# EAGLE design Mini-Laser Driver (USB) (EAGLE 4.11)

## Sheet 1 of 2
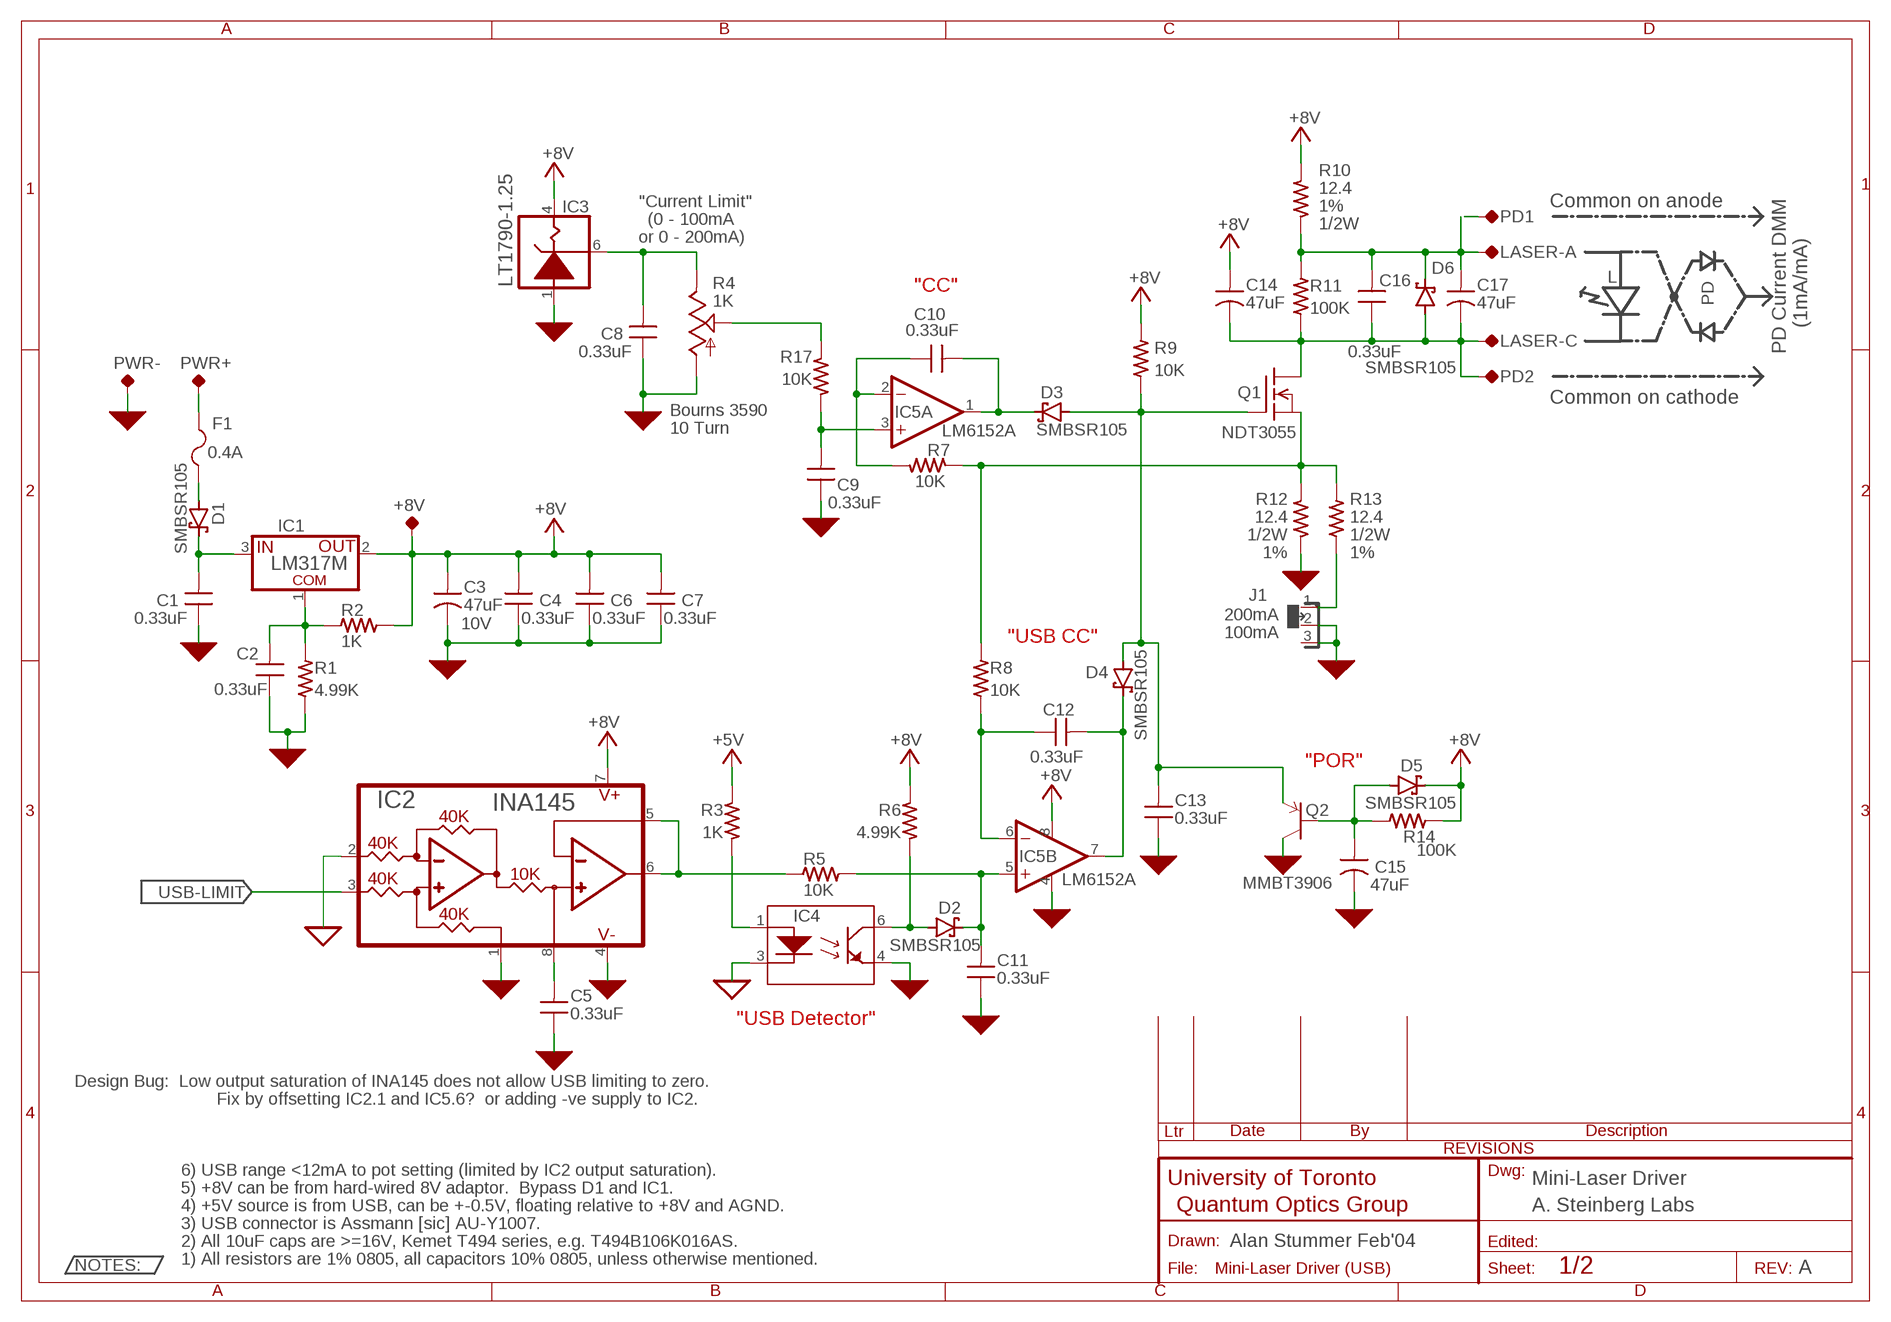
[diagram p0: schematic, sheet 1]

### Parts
+8V  TP-HOLE-0.042  [TP-HOLE]
C1  0.33uF  CAP-V-SMT0805  [0805@1]
C2  0.33uF  CAP-V-SMT0805  [0805@1]
C3  47uF  CAP-POL-EIA-B  [EIA-B]
C4  0.33uF  CAP-V-SMT0805  [0805@1]
C5  0.33uF  CAP-V-0805  [0805]
C6  0.33uF  CAP-V-SMT0805  [0805@1]
C7  0.33uF  CAP-V-SMT0805  [0805@1]
C8  0.33uF  CAP-V-SMT0805  [0805@1]
C9  0.33uF  CAP-V-0805  [0805]
C10  0.33uF  CAP-H-SMT0805  [0805@1]
C11  0.33uF  CAP-V-0805  [0805]
C12  0.33uF  CAP-H-SMT0805  [0805@1]
C13  0.33uF  CAP-V-0805  [0805]
C14  47uF  CAP-POL-EIA-B  [EIA-B]
C15  47uF  CAP-POL-EIA-B  [EIA-B]
C16  0.33uF  CAP-V-0805  [0805]
C17  47uF  CAP-POL-EIA-B  [EIA-B]
D1  SMBSR105  SMBSR105-MSCT  [DO-214AA]
D2  SMBSR105  SMBSR105-MSCT  [DO-214AA]
D3  SMBSR105  SMBSR105-MSCT  [DO-214AA]
D4  SMBSR105  SMBSR105-MSCT  [DO-214AA]
D5  SMBSR105  SMBSR105-MSCT  [DO-214AA]
D6  SMBSR105  SMBSR105-MSCT  [DO-214AA]
F1  0.4A  FUSE5X20-2  [FUSE5X20-2]
IC1  LM317M  LM317D2  [D2PAK]
IC2  INA145UA  [SOIC-8]
IC3  LT1790-1.25  LT1790BCS6-1.25  [SOT23-6]
IC4  TLP181  [SOIC-6]
IC5  LM6152A  LT1807CS8  [SOIC-8]
J1  JUMPER-1X3-3  [JUMPER-3]
LASER-A  TP-HOLE-0.042  [TP-HOLE]
LASER-C  TP-HOLE-0.042  [TP-HOLE]
PD1  TP-HOLE-0.042  [TP-HOLE]
PD2  TP-HOLE-0.042  [TP-HOLE]
PWR+  TP-HOLE-0.042  [TP-HOLE]
PWR-  TP-HOLE-0.042  [TP-HOLE]
Q1  NDT3055  [SOT223]
Q2  MMBT3906  BJT-PNP-SOT23  [SOT23]
R1  4.99K  R-V-0805  [0805]
R2  1K  R-H-0805  [0805]
R3  1K  R-V-0805  [0805]
R4  1K  POT-3590  [3590_BOURNS]
R5  10K  R-H-0805  [0805]
R6  4.99K  R-V-0805  [0805]
R7  10K  R-H-0805  [0805]
R8  10K  R-V-0805  [0805]
R9  10K  R-V-0805  [0805]
R10  12.4  R-V-THRU  [PASSIVE_0.4"]
R11  100K  R-V-0805  [0805]
R12  12.4  R-V-THRU  [PASSIVE_0.4"]
R13  12.4  R-V-THRU  [PASSIVE_0.4"]
R14  100K  R-H-0805  [0805]
R17  10K  R-V-0805  [0805]

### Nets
+1.23V: C8.2 IC3.6(OUT) R4.CW
+5V [Fat Track 0.025"]: R3.2 ; also sheet 2
+8V [Fat Track 0.025"]: +8V.P$1(TP) C3.2(POS) C4.2 C6.2 C7.2 C14.2(POS) D5.K(C) IC1.2(VO) IC2.7(V+) IC3.4(IN) IC5.8(V+) R2.2 R6.2 R9.2 R10.2 R14.2
AGND [Fat Track 0.025"]: C1.1 C2.1 C3.1(NEG) C4.1 C5.1 C6.1 C7.1 C8.1 C9.1 C11.1 C13.1 C15.1(NEG) IC2.1(IN-REF) IC2.4(V-) IC3.1(COM) IC4.4(E) IC5.4(V-) J1.2 J1.3 PWR-.P$1(TP) Q2.3(C) R1.1 R4.CCW R12.1
CC-LEVEL: C9.2 IC5.3(A:+IN) R17.1
GND2 [Fat Track 0.025"]: IC2.2(IN-) IC4.3(K) ; also sheet 2
I-LASER [Fat Track 0.025"]: Q1.3(S) R7.1 R8.2 R12.2 R13.2
LASER-A [Fat Track 0.025"]: C16.2 C17.2(POS) D6.K(C) LASER-A.P$1(TP) PD1.P$1(TP) R10.1 R11.2
LASER-C [Fat Track 0.025"]: C14.1(NEG) C16.1 C17.1(NEG) D6.A LASER-C.P$1(TP) PD2.P$1(TP) Q1.2(D) R11.1
LIMIT: C13.2 D3.A D4.A Q1.1(G) Q2.2(E) R9.1
N$1: C10.1 D3.K(C) IC5.1(A:OUT)
N$2 [Fat Track 0.025"]: D2.A IC4.6(C) R6.1
N$3: IC2.5(RG) IC2.6(OUT) R5.1
N$4 [Fat Track 0.025"]: J1.1 R13.1
N$5: C10.2 IC5.2(A:-IN) R7.2
N$7 [Fat Track 0.025"]: C5.2 IC2.8(VOI)
N$8 [Fat Track 0.025"]: IC4.1(A) R3.1
N$11 [Fat Track 0.025"]: D1.A F1.1(1A)
N$15: C2.2 IC1.1(COM) R1.2 R2.1
N$16: C12.1 D4.K(C) IC5.7(B:OUT)
N$17: C12.2 IC5.6(B:-IN) R8.1
N$20 [Fat Track 0.025"]: C1.2 D1.K(C) IC1.3(VI)
N$24 [Fat Track 0.025"]: F1.2(2A) PWR+.P$1(TP)
N$25 [Fat Track 0.025"]: R4.W R17.2
POR: C15.2(POS) D5.A Q2.1(B) R14.1
USB-CC-LIMIT: C11.2 D2.K(C) IC5.5(B:+IN) R5.2
Unconnected: IC2.3(IN+)

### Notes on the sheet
- PD Current DMM
- "Current Limit" | 1% | Common on anode
- (0 - 100mA | 1/2W
- or 0 - 200mA)
- L
- "CC"
- PD
- (1mA/mA)
- Common on cathode
- Bourns 3590
- 10 Turn
- 1/2W | 1/2W
- 1% | 1%
- 200mA
- 10V
- "USB CC" | 100mA
- "POR"
- "USB Detector"
- Design Bug:  Low output saturation of INA145 does not allow USB limiting to zero.
- Fix by offsetting IC2.1 and IC5.6?  or adding -ve supply to IC2.
- 6) USB range <12mA to pot setting (limited by IC2 output saturation).
- Mini-Laser Driver
- 5) +8V can be from hard-wired 8V adaptor.  Bypass D1 and IC1.
- 4) +5V source is from USB, can be +-0.5V, floating relative to +8V and AGND. | A. Steinberg Labs
- 3) USB connector is Assmann [sic] AU-Y1007.
- 2) All 10uF caps are >=16V, Kemet T494 series, e.g. T494B106K016AS. | Alan Stummer Feb'04
- 1) All resistors are 1% 0805, all capacitors 10% 0805, unless otherwise mentioned.
- A

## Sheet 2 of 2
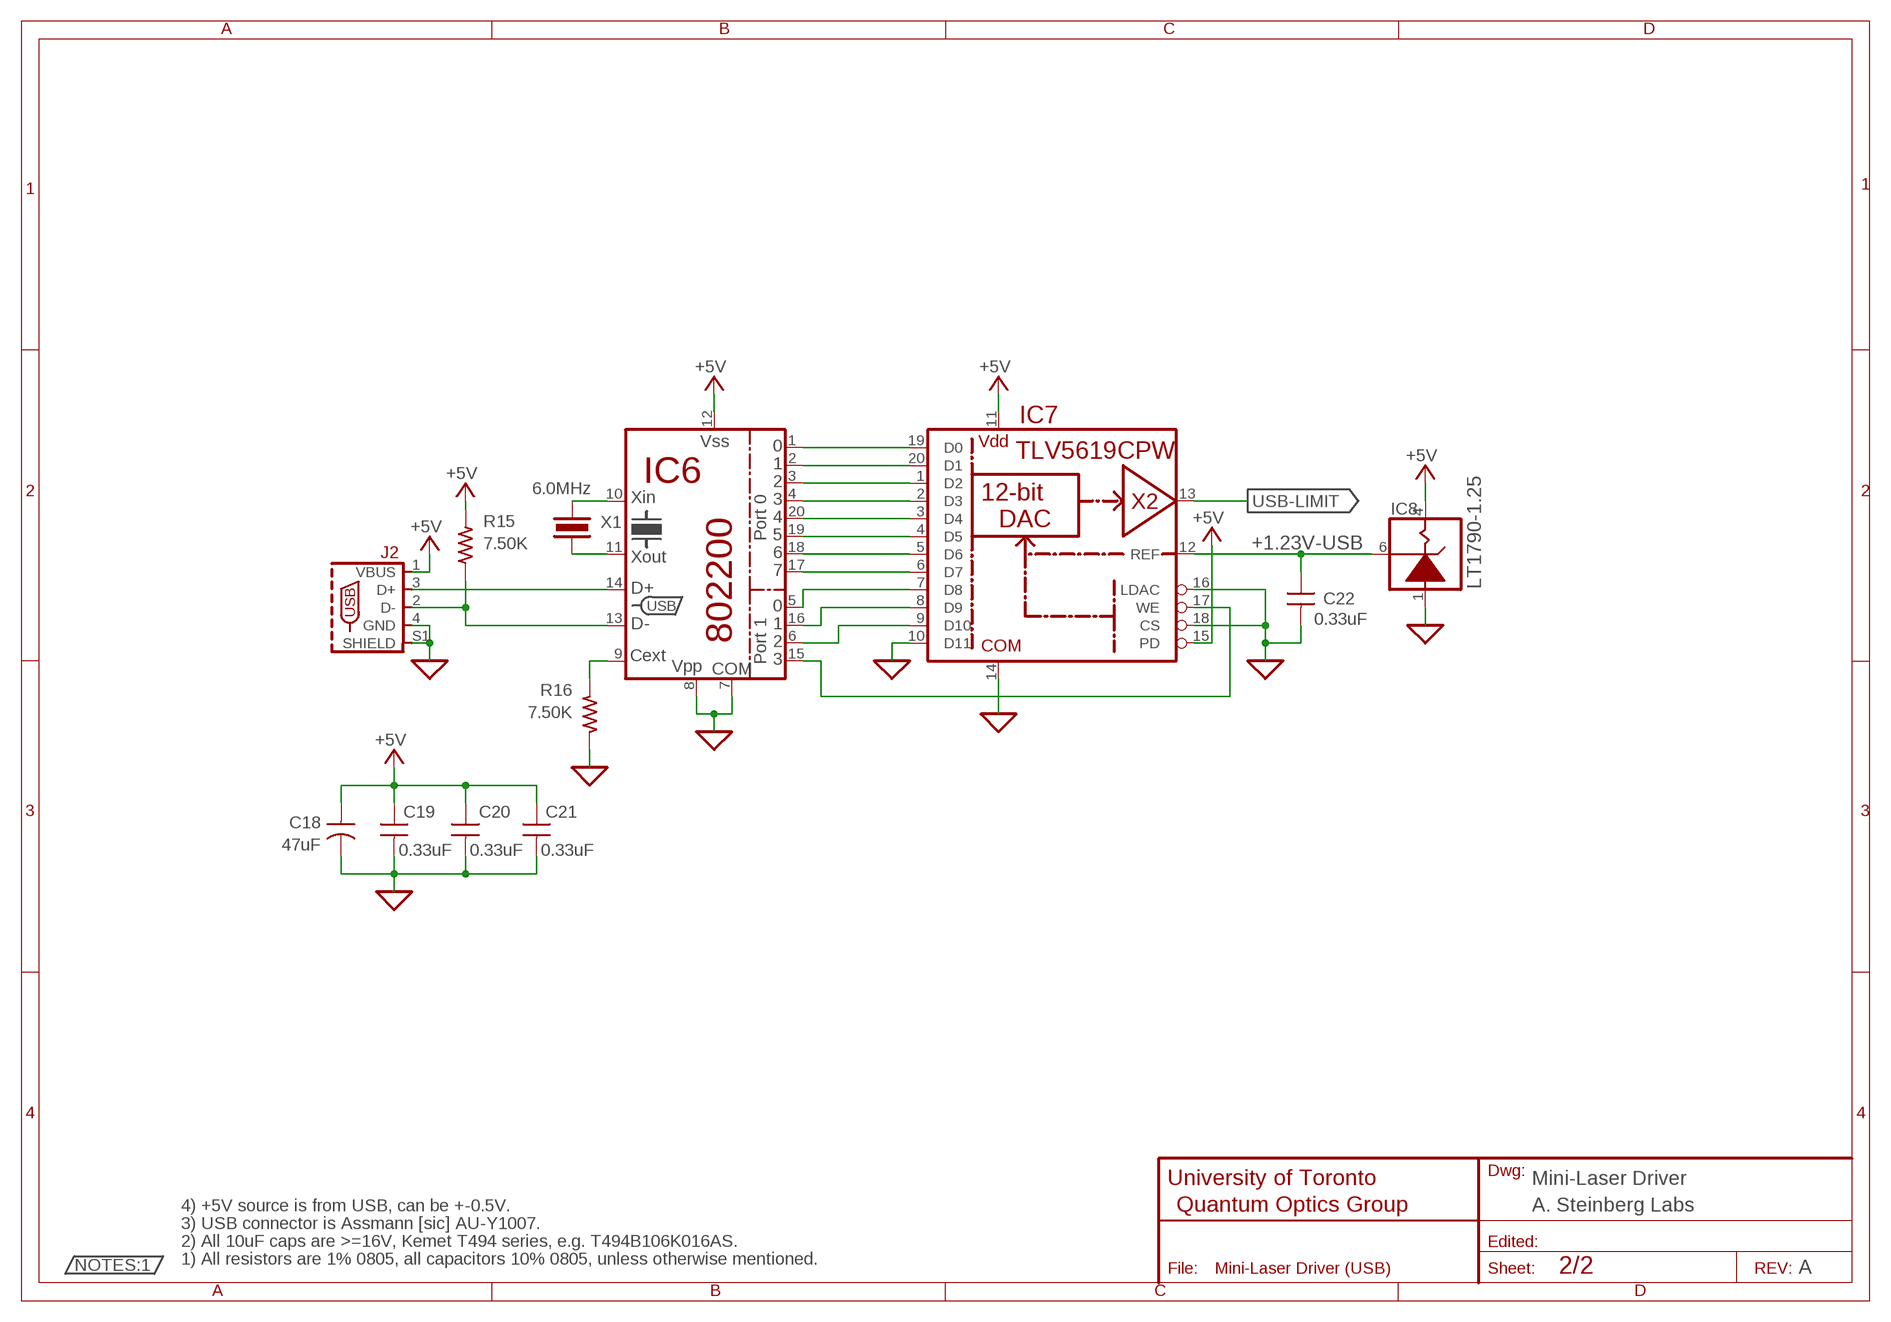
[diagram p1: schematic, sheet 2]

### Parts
C18  47uF  CAP-POL-EIA-B  [EIA-B]
C19  0.33uF  CAP-H-0805  [0805]
C20  0.33uF  CAP-H-0805  [0805]
C21  0.33uF  CAP-H-0805  [0805]
C22  0.33uF  CAP-H-0805  [0805]
IC6  802200  802200(DELCOMUSB)-SO20  [SOIC-20W]
IC7  TLV5619CPW  [TSSOP-20]
IC8  LT1790-1.25  LT1790BCS6-1.25  [SOT23-6]
J2  AU-Y1007-USB-B  [CONN-USB_AU-Y1007]
R15  7.50K  R-V-0805  [0805]
R16  7.50K  R-V-0805  [0805]
X1  6.0MHz  XTAL/RESONATOR-P  [RESONATOR-P]

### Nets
+1.23V-USB: C22.2 IC7.12(REF) IC8.6(OUT)
+5V [Fat Track 0.025"]: C18.2(POS) C19.2 C20.2 C21.2 IC6.12(VCC) IC7.11(VDD) IC7.15(PD) IC8.4(IN) J2.1(VBUS) R15.2 ; also sheet 1
GND2 [Fat Track 0.025"]: C18.1(NEG) C19.1 C20.1 C21.1 C22.1 IC6.7(COM) IC6.8(VPP) IC7.10(D11) IC7.14(COM) IC7.16(LDAC) IC7.18(CS) IC8.1(COM) J2.4(GND) J2.S1(SHIELD) R16.1 ; also sheet 1
N$6: IC6.9(CEXT) R16.2
N$46: IC6.10(XTL1) X1.2(X2)
N$47: IC6.11(XTL2) X1.1(X1)
N$49: IC6.1(P0.0) IC7.19(D0)
N$50: IC6.2(P0.1) IC7.20(D1)
N$51: IC6.3(P0.2) IC7.1(D2)
N$52: IC6.4(P0.3) IC7.2(D3)
N$53: IC6.20(P0.4) IC7.3(D4)
N$54: IC6.19(P0.5) IC7.4(D5)
N$55: IC6.18(P0.6) IC7.5(D6)
N$56: IC6.17(P0.7) IC7.6(D7)
N$57: IC6.5(P1.0) IC7.7(D8)
N$58: IC6.16(P1.1) IC7.8(D9)
N$59: IC6.6(P1.2) IC7.9(D10)
USB-D+1: IC6.14(D+) J2.3(D+)
USB-D-1: IC6.13(D-) J2.2(D-) R15.1
USB-LIMIT: IC7.13(OUT) ; also sheet 1
~WE1: IC6.15(P1.3) IC7.17(WE)

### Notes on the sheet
- Mini-Laser Driver
- 4) +5V source is from USB, can be +-0.5V. | A. Steinberg Labs
- 3) USB connector is Assmann [sic] AU-Y1007.
- 2) All 10uF caps are >=16V, Kemet T494 series, e.g. T494B106K016AS.
- 1) All resistors are 1% 0805, all capacitors 10% 0805, unless otherwise mentioned.
- A

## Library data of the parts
+8V LASER-A LASER-C PD1 PD2 PWR+ PWR- = 0-UofT-Physics:TP: Testpoint, test point on schematic, small pad on PCB.
C1 C2 C4 C6-C8 = 0-UofT-Physics:CAP-V-SMT*: Cap, SMT 0805
C3 C14 C15 C17 C18 = 0-UofT-Physics:CAP-POL-: Capacitor, Polarized, electrolytic (tantalum)l.
C5 C9 C11 C13 C16 = 0-UofT-Physics:CAP-V-: Cap, SMT, 0402 to 1206
C10 C12 = 0-UofT-Physics:CAP-H-SMT*: Cap, SMT 0805
C19-C22 = 0-UofT-Physics:CAP-H-: Cap, SMT, 0402 to 1206
D1-D6 = 0-UofT-Physics:SMBSR105: SMBSR105, MCC, Schottky 50V 1A SMT, general purpose, Vf=0.4V@1A, Ir=3uA@5V@25°(poor).
F1 = 0-UofT-Physics:FUSE: Fuse
IC1 = 0-UofT-Physics:LM317: LM317, bandgap based adjustable regulator.
IC2 = 0-UofT-Physics:INA145: INA145, Burr-Brown/T.I., instrumentation amp, CMR >85dB, 2(V-) < Vcm < 2(V+)-2.
IC3 IC8 = 0-UofT-Physics:LT1790: LT1790, series reference in SOT-23-6. From 1.25V to 5.0V with common binary voltages. Likes 1uF or more load, 0.1uF or more source.
IC4 = 0-UofT-Physics:TLP181: Opto-coupler, Toshiba, general purpose, 3.75KV, Vce 50%, If < 50mA, 150mW.
IC5 = 0-UofT-Physics:LT1807*: Op Amp, dual, single supply, RRIO, fast (GBW 350MHz, 100V/uS). Great part, but Ib = 4uA max.
IC6 = 0-UofT-Physics:802200(DELCOMUSB): 802200 USB Peripheral, Delcom, quick and dirty USB 1.0 peripheral solution.
IC7 = 0-UofT-Physics:TLV5619
J1 = 0-UofT-Physics:JUMPER-1X3: Jumper, header, SIP on 0.1" grid, for option selection.
J2 = 0-UofT-Physics:AU-Y1007
Q1 = 0-UofT-Physics:NDT3055: NDT3055, Fairchild, N-channel MOSFET. SOT-223, 4A, 60V, 3Wmax, 0.1 Ohm at Vgs=10V.
Q2 = 0-UofT-Physics:BJT-PNP: PNP BJT, generic, p/n defined by VALUE field. E.g. Fairchild MMBT3906 (abs max 40V, 200mA. hFE>80@10mA.
R1 R3 R6 R8-R13 R15-R17 = 0-UofT-Physics:R-V-*: Resistor, SMT, vertical symbol
R2 R5 R7 R14 = 0-UofT-Physics:R-H-*: Resistor, SMT, horizontal symbol
R4 = 0-UofT-Physics:POT: Pot, regular or trimpot
X1 = 0-UofT-Physics:XTAL/RESONATOR: Crystal or Reonator. Besure to verify package, especially SMT pads sizes and locations.

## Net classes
1 Fat Track 0.025": width 0.635 mm, drill 0.254 mm

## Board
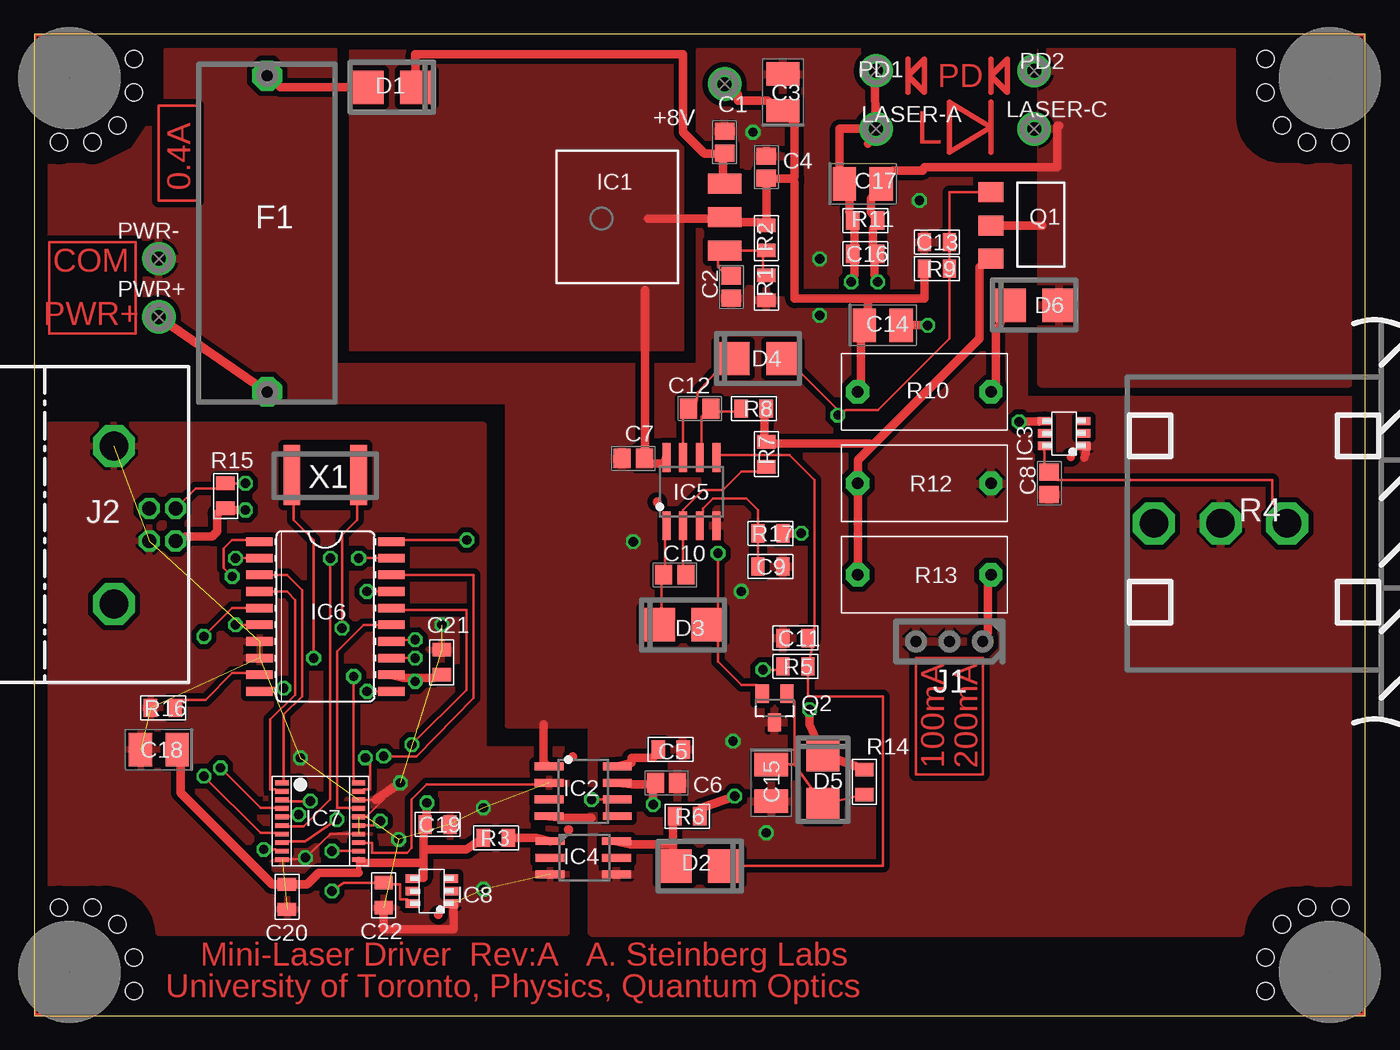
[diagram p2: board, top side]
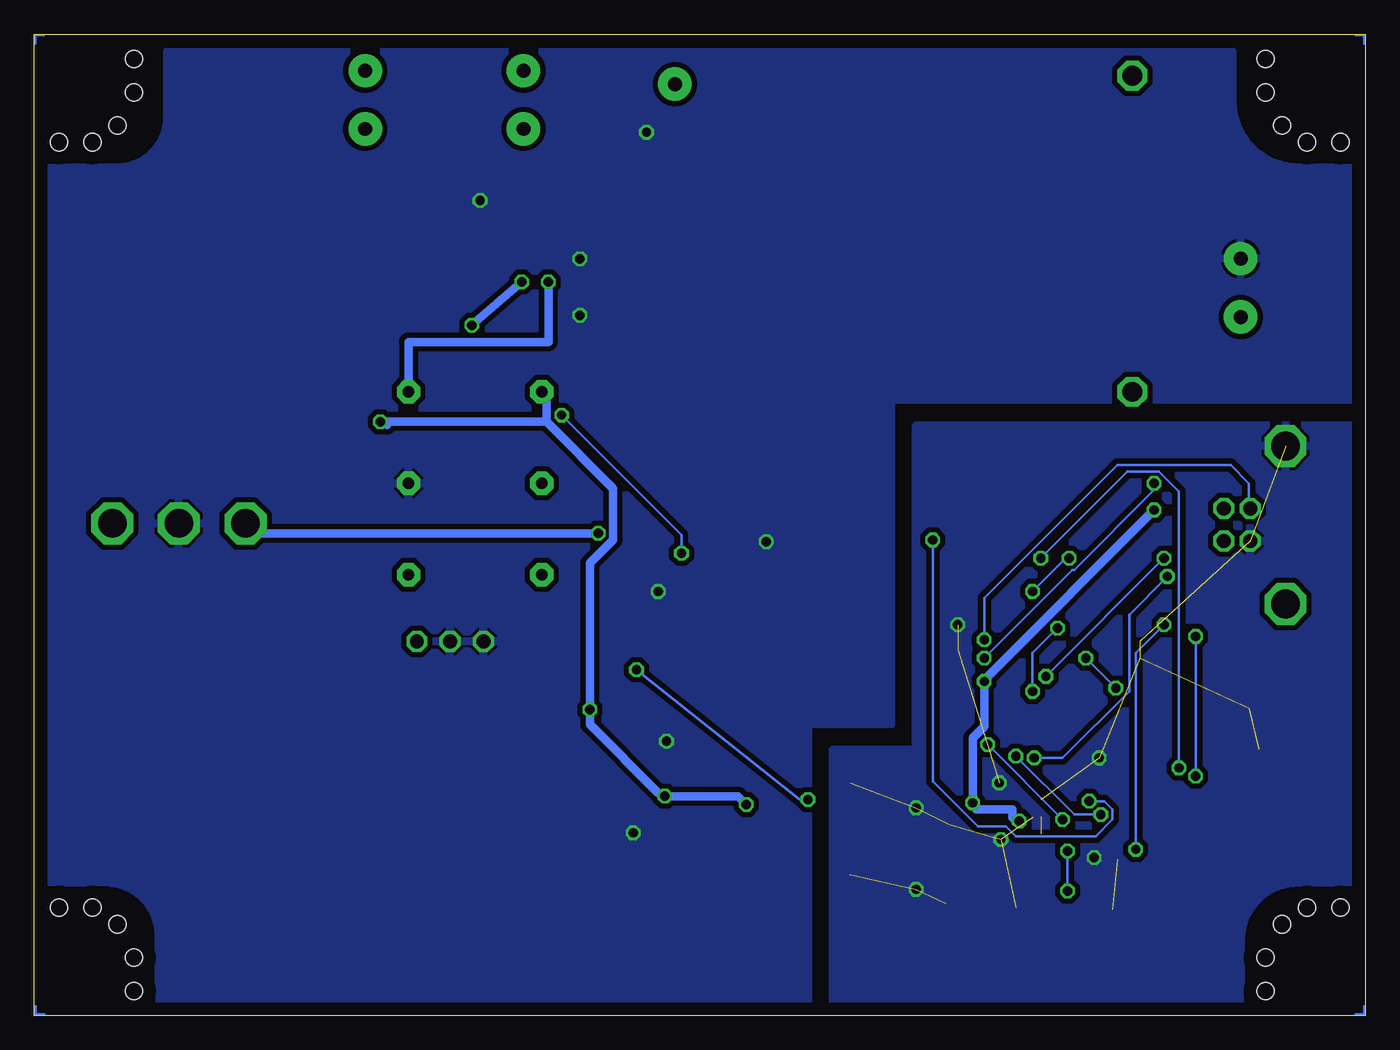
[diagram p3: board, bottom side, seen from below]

Size 101.6 x 74.93 mm. Coordinates in mm from the lower left corner, seen from the top.
Outline: 0,0 101.6,0 101.6,74.93 0,74.93 0,0
Copper layers (1*16): Top 0.035mm / dielectric 1.5mm / Bottom 0.035mm
Design rules "default": minimum track width 8mil, minimum drill 28mil, track to track 8mil, track to pad 8mil, pad to pad 8mil, via to via 8mil, smd to smd 8mil, copper to edge 40mil, drill to drill 8mil, minimum pad ring 10mil, minimum via ring 8mil, stop-mask expansion 4mil, vias tented up to drill 0mil, thermal gap 10mil
Holes 1.32 mm at 99.69,8.26 93.98,1.91 95.25,6.99 97.16,8.26 93.98,4.45 1.91,8.26 7.62,1.91 6.35,6.99 4.45,8.26 7.62,4.45 1.91,66.67 7.62,73.03 6.35,67.94 4.45,66.67 7.62,70.48 99.69,66.67 93.98,73.03 95.25,67.94 97.16,66.67 93.98,70.48

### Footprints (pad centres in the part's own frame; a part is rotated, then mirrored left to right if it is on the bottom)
TP-HOLE = drill 1.067 pad 2.54 round: P$1 0,0
0805@1 = smd 1.3 x 1.5: 1 -0.85,0; 2 0.85,0
EIA-B = smd 1.778 x 2.54: 1 -1.4,0; 2 1.4,0
0805 = smd 1.016 x 1.397: 1 -1.905,0; 2 0,0
DO-214AA = smd 2.54 x 2.54: A -1.905,0; K 1.905,0
FUSE5X20-2 = drill 1.511 octagon: 1 -12.065,0; 2 12.065,0
D2PAK = smd 1.524 x 2.54: 1 -2.54,-2.54; 2 0,-2.54; 3 2.54,-2.54
SOIC-8 = smd 0.6 x 2.2: 1 -1.27,-2.6; 2 0,-2.6; 3 1.27,-2.6; 4 2.54,-2.6; 5 2.54,2.6; 6 1.27,2.6; 7 0,2.6; 8 -1.27,2.6
SOT23-6 = smd 0.635 x 0.991: 1 -0.95,-0.099; 2 0,-0.099; 3 0.95,-0.099; 4 0.95,2.901; 5 0,2.901; 6 -0.95,2.901
SOIC-6 = smd 0.6 x 2.2: 1 -1.27,-2.54; 2 0,-2.54; 3 1.27,-2.54; 4 1.27,2.54; 5 0,2.54; 6 -1.27,2.54
SOIC-20W = smd 0.66 x 2.032: 1 -5.715,-5.029; 2 -4.445,-5.029; 3 -3.175,-5.029; 4 -1.905,-5.029; 5 -0.635,-5.029; 6 0.635,-5.029; 7 1.905,-5.029; 8 3.175,-5.029; 9 4.445,-5.029; 10 5.715,-5.029; 11 5.715,5.029; 12 4.445,5.029; 13 3.175,5.029; 14 1.905,5.029; 15 0.635,5.029; 16 -0.635,5.029; 17 -1.905,5.029; 18 -3.175,5.029; 19 -4.445,5.029; 20 -5.715,5.029
TSSOP-20 = smd 0.356 x 1.016: 1 0,-5.85; 2 0.65,-5.85; 3 1.3,-5.85; 4 1.95,-5.85; 5 2.6,-5.85; 6 3.25,-5.85; 7 3.9,-5.85; 8 4.55,-5.85; 9 5.2,-5.85; 10 5.85,-5.85; 11 5.85,0; 12 5.2,0; 13 4.55,0; 14 3.9,0; 15 3.25,0; 16 2.6,0; 17 1.95,0; 18 1.3,0; 19 0.65,0; 20 0,0
JUMPER-3 = drill 1.067 octagon: 1 0,2.54; 2 0,0; 3 0,-2.54
CONN-USB_AU-Y1007 = drill 1.067 octagon: 1 2.5,0; 2 0,0; 3 0,-2; 4 2.5,-2 | drill 2.184 octagon: S1 -4.75,-4.7; S2 7.3,-4.7
SOT223 = smd 1.524 x 1.905: 1 -2.54,-2.54; 2 0,-2.54; 3 2.54,-2.54
SOT23 = smd 1 x 1.4: 1 -0.95,-1.1; 2 0.95,-1.1; 3 0,1.1
3590_BOURNS = drill 2.184 octagon: CCW -12.065,0; CW -6.985,0; W -17.145,0
PASSIVE_0.4" = drill 0.889 pad 1.778 octagon: 1 -5.08,0; 2 5.08,0
RESONATOR-P = smd 1.27 x 4.572: 1 -2.54,0; 2 2.54,0

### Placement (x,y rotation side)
+8V  52.7,71.12 90 top
C1  52.7,66.67 270 top
C2  53.21,55.63 90 top
C3  57.15,70.48 270 top
C4  55.88,64.77 270 top
C5  47.62,20.32 180 top
C6  48.26,17.78 180 top
C7  45.72,42.55 0 top
C8  77.47,40.64 90 top
C9  55.24,34.29 180 top
C10  48.9,33.66 0 top
C11  59.05,28.83 0 top
C12  50.8,46.35 0 top
C13  69.85,59.05 0 top
C14  64.77,52.7 180 top
C15  56.26,17.78 90 top
C16  62.48,58.17 180 top
C17  63.25,63.5 180 top
C18  9.53,20.32 0 top
C19  29.84,14.61 180 top
C20  19.3,10.03 90 top
C21  31.11,26.04 270 top
C22  26.67,10.16 90 top
D1  27.3,70.87 0 top
D2  50.8,11.43 0 top
D3  49.53,29.84 180 top
D4  55.24,50.16 180 top
D5  60.2,18.03 90 top
D6  76.33,54.23 180 top
F1  17.78,59.69 270 top
IC1  50.16,60.96 90 top
IC2  41.91,17.78 270 top
IC3  80.01,44.45 90 top
IC4  41.91,12.06 270 top
IC5  49.53,40.01 0 top
IC6  22.23,30.48 270 top
IC7  24.77,17.78 270 top
IC8  31.75,9.53 90 top
J1  69.85,28.57 270 top
J2  10.79,38.73 270 top
LASER-A  64.26,67.69 90 top
LASER-C  76.33,67.69 0 top
PD1  64.26,72.14 90 top
PD2  76.33,72.14 90 top
PWR+  9.53,53.34 0 top
PWR-  9.53,57.78 0 top
Q1  75.56,60.33 270 top
Q2  56.52,23.5 180 top
R1  55.88,56.52 90 top
R2  55.88,60.33 90 top
R3  34.29,13.59 180 top
R4  102.62,37.59 0 top
R5  59.05,26.67 0 top
R6  50.8,15.24 0 top
R7  55.88,41.91 270 top
R8  55.88,46.35 0 top
R9  67.94,57.02 180 top
R10  67.94,47.62 180 top
R11  62.48,60.71 180 top
R12  67.94,40.64 180 top
R13  67.94,33.66 180 top
R14  63.37,18.8 90 top
R15  14.61,38.73 270 top
R16  10.79,23.5 0 top
R17  57.15,36.83 0 top
U$29  [TARGET]  not placed on the board
U$30  [TARGET]  not placed on the board
U$31  [TARGET]  not placed on the board
U$32  [TITLEBLOCK_PCB]  not placed on the board
X1  22.23,41.27 180 top

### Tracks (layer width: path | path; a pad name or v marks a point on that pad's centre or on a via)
+1.23V
  Top 0.203: IC3.6 77.09,43.31 77.09,42.04 C8.2 78.11,40.89 94.49,40.89 94.49,39.24 R4.CW
+1.23V-USB  (via drill 0.71)
  Top 0.203: IC8.6 28.45,8.89 27.94,8.89 27.94,10.03 27.3,10.03 C22.2 23.62,10.16 v22.73,9.53 | v22.73,12.57 IC7.12
  Bottom 0.203: v22.73,9.53 v22.73,12.57
+5V  (via drill 0.71)
  Top 0.203: IC7.15 26.09,14.53 v26.42,14.86 | IC7.11 25.15,11.68
  Top 0.406: 24.77,10.92 IC7.11
  Top 0.635: C18.2 11.18,19.18 11.18,17.02 18.16,10.03 C20.2 20.83,10.03 21.72,10.92 24.77,10.92 | J2.1 11.56,36.58 13.59,36.58 13.97,36.96 13.97,38.35 R15.2 15.24,38.61 v16.13,38.61 | 29.08,25.78 28.19,25.78 IC6.12 | 29.08,25.78 30.48,25.78 C21.2 | 29.72,11.68 29.72,10.54 IC8.4 | 29.72,11.68 29.72,12.7 | 29.72,12.7 29.72,13.97 C19.2 29.97,15.24 v29.97,16.26 | 25.15,11.68 29.72,11.68 | R3.2 33.02,12.7 29.72,12.7 | v29.08,25.53 29.08,25.78
  Bottom 0.635: v16.13,38.61 28.83,25.91 v29.08,25.53 29.08,22.1 29.97,21.21 v29.97,16.26 29.72,15.75 26.92,15.75 26.92,15.11 v26.42,14.86
+8V  (via drill 0.71)
  Top 0.635: v53.47,16.76 50.93,15.88 R6.2 | v47.24,16.13 47.24,17.14 C6.2 46.86,17.65 45.59,17.65 IC2.7 | 63.63,54.74 67.94,54.74 R9.2 | 63.63,54.74 63.63,53.85 C14.2 63.12,51.56 63.12,48.39 R10.2 | +8V.P$1 53.72,70.36 53.72,69.85 56.01,69.85 C3.2 58.04,68.2 58.04,64.01 57.91,63.88 | IC5.8 48.01,42.16 47.12,42.16 C7.2 46.61,43.18 46.61,55.37 | 46.86,60.83 51.82,60.83 IC1.2 53.59,60.58 55.24,60.58 R2.2 C4.2 56.52,63.88 57.91,63.88 | 63.63,54.74 58.04,54.74 58.04,63.63 57.91,63.88 | R14.2 D5.K 59.18,22.23 v59.18,23.37 | v75.18,45.34 76.71,45.34 IC3.4
  Bottom 0.635: v47.24,16.13 47.88,16.76 v53.47,16.76 53.98,17.02 59.18,22.23 v59.18,23.37 59.18,34.54 57.4,36.32 57.4,40.26 62.48,45.34 | 62.48,45.34 62.48,46.86 R10.2 | 62.48,45.34 74.68,45.34 | 74.68,45.34 75.06,45.34 | v75.18,45.34 74.68,45.09 74.68,45.34
  pour Top (isolate 0.406): 24.13,73.66 24.13,50.8 49.53,50.8 49.53,73.66
AGND  (via drill 0.71)
  Top 0.635: 38.86,22.23 38.86,19.3 IC2.1 | 42.55,15.11 40.39,15.11 IC2.4 | IC3.1 80.26,43.31 80.26,42.93 80.15,42.62
  other vias: 45.72,36.2 53.98,32.38 59.94,57.78 59.94,53.47 53.34,20.95 55.88,13.97 54.86,67.44 67.56,62.23
  pour Bottom (isolate 0.406): 10.16,73.66 10.16,69.85 arc-90 5.08,64.77 0.64,64.77 0.64,46.99 36.2,46.99 36.2,22.23 42.55,22.23 42.55,0.64 92.08,0.64 92.08,6.35 arc-90 96.52,10.16 100.97,10.16 100.97,64.77 95.25,64.77 arc-90 91.44,68.58 91.44,73.66
  pour Top (isolate 0.406): 50.8,73.66 50.8,49.53 22.86,49.53 22.86,73.66 10.16,73.66 10.16,69.85 7.62,66.04 5.08,64.77 0.64,64.77 0.64,46.99 36.2,46.99 36.2,22.23 42.55,22.23 42.55,6.35 92.08,6.35 arc-90 96.52,10.16 100.97,10.16 100.97,46.99 75.56,46.99 75.56,73.66
CC-LEVEL
  Top 0.203: C9.2 R17.1 55.24,38.61 54.36,39.5 51.82,39.5 51.05,38.73 51.05,38.48 IC5.3
GND2  (via drill 0.71)  (18 unrouted)
  Top 0.203: IC7.14 23.15,13.88 22.61,13.84 v20.7,12.06 19.93,11.94 IC7.10 | 26.07,16.48 IC7.18 | IC7.16 25.34,15.18 v27.94,17.78 | 32,8.57 IC8.1
  Top 0.635: v27.94,17.78 26.07,16.48 | 32,8.57 32,6.6 26.67,6.6 C22.1
  other vias: 34.29,15.88 31.11,29.84 27.81,13.46 20.32,19.68 34.29,9.65
  pour Top (isolate 0.406): 0,45.09 0,10.16 5.08,10.16 arc-90 9.53,6.35 40.64,6.35 40.64,20.32 34.29,20.32 34.29,45.09
  pour Bottom (isolate 0.406): 0,45.09 0,10.16 5.08,10.16 arc-90 9.53,5.71 9.53,0.64 40.64,0.64 40.64,20.32 34.29,20.32 34.29,45.09
I-LASER
  Top 0.635: R8.2 55.75,45.72 55.75,44.2 R7.1 56.52,43.69 63.75,43.69 63.94,43.5 | 63.94,43.5 62.87,42.42 R12.2 R13.2 | 63.94,43.5 72.14,51.69 72.14,57.15 Q1.3
LASER-A  (via drill 0.71)
  Top 0.635: PD1.P$1 64.14,71.75 LASER-A.P$1 | D6.K 73.41,52.2 73.41,48.39 R10.1 | LASER-A.P$1 63.63,66.55 | v62.36,56.01 62.61,56.52 62.61,57.53 C16.2 62.61,58.8 62.61,60.07 R11.2 62.23,61.34 62.23,62.36 C17.2 61.47,64.64 61.47,67.69 LASER-A.P$1
  Bottom 0.635: v62.36,56.01 62.36,51.44 73.03,51.44 R10.1
LASER-C  (via drill 0.71)
  Top 0.635: Q1.2 76.96,60.33 | C14.1 v68.2,52.7 | 78.23,67.94 78.11,67.94 78.11,64.77 67.94,64.77 67.82,64.52 65.53,64.52 C17.1 63.88,62.36 63.88,61.34 R11.1 64.01,60.07 64.01,58.8 C16.1 64.14,57.53 64.14,56.52 v64.39,56.01
  Bottom 0.635: v68.2,52.7 v64.39,56.01
  pour Top (isolate 0.406): 76.83,73.66 76.83,48.26 100.33,48.26 100.33,64.77 95.25,64.77 arc-90 91.44,68.58 91.44,73.66
LIMIT  (via drill 0.71)
  Top 0.203: Q2.2 55.12,25.27 53.98,25.27 52.2,27.05 52.2,28.7 D3.A 52.2,30.99 v52.2,35.31 | 61.53,46.04 61.98,46.23 64.39,46.23 69.85,51.69 R9.1 C13.2 69.85,62.87 Q1.1 | 61.53,46.04 58.55,49.02 57.66,49.02 D4.A | v61.34,45.85 61.53,46.04
  Bottom 0.203: v52.2,35.31 52.2,36.7 v61.34,45.85
N$1
  Top 0.203: D3.K 47.88,30.99 47.88,33.02 C10.1 48.13,34.29 48.13,36.32 IC5.1
N$2
  Top 0.635: 48.77,13.08 48.77,12.57 D2.A | 48.77,13.08 48.77,14.61 R6.1 | IC4.6 45.47,13.08 48.77,13.08
N$3  (via drill 0.71)
  Top 0.203: v55.63,26.42 56.77,26.42 R5.1 | v42.55,16.51 IC2.6 43.69,16.26 43.69,15.49 IC2.5
  Bottom 0.203: v55.63,26.42 43.18,16.51 v42.55,16.51
N$4
  Top 0.635: J1.1 72.77,29.21 72.77,32.89 R13.1
N$5
  Top 0.203: R7.2 55.24,41.53 53.98,41.53 52.58,40.13 51.05,40.13 49.53,38.61 IC5.2 49.53,34.29 C10.2
N$6
  Top 0.203: R16.2 11.18,24.13 13.08,24.13 15.11,26.16 16.26,26.16 IC6.9
N$7
  Top 0.635: C5.2 47.24,19.68 45.59,19.68 45.59,19.3 IC2.8
N$8
  Top 0.635: R3.1 38.35,13.59 IC4.1
N$9
  Bottom 0.203: 0.1,0.74 0.1,0.1 0.74,0.1
N$10
  Top 0.203: 0.1,0.74 0.1,0.1 0.74,0.1
N$11
  Top 0.635: D1.A 18.8,70.87 F1.1
N$12
  Bottom 0.203: 0.74,74.83 0.1,74.83 0.1,74.19
N$13
  Top 0.203: 0.74,74.83 0.1,74.83 0.1,74.19
N$14
  Bottom 0.203: 101.5,74.19 101.5,74.83 100.86,74.83
N$15
  Top 0.203: R1.2 55.63,56.9 55.63,58.04 R2.1 IC1.1 52.2,57.78 52.2,57.15 52.83,56.52 52.83,56.48 C2.2
N$16
  Top 0.203: IC5.7 49.53,45.72 C12.1 50.55,46.86 50.67,47.62 51.94,49.02 D4.K
N$17
  Top 0.203: R8.1 53.59,46.1 52.2,46.1 C12.2 51.05,45.85 50.93,45.72 50.93,43.69 IC5.6
N$20
  Top 0.635: IC1.3 52.58,64.14 52.58,65.28 C1.2 52.7,65.79 51.18,65.79 49.53,67.44 49.53,73.41 29.08,73.41 D1.K
N$21
  Top 0.203: 101.5,74.19 101.5,74.83 100.86,74.83
N$22
  Bottom 0.203: 100.84,0.1 101.47,0.1 101.47,0.74
N$23
  Top 0.203: 100.84,0.1 101.47,0.1 101.47,0.74
N$24
  Top 0.635: PWR+.P$1 F1.2
N$25  (via drill 0.71)
  Top 0.635: R17.2 v58.55,36.83
  Bottom 0.635: v58.55,36.83 85.47,36.83 R4.W
N$26
  Top 0.203: 67.31,18.41 67.31,27.3 72.39,27.3 72.39,18.41 67.31,18.41
N$27
  Top 0.203: 1.14,59.05 7.75,59.05 7.75,52.07 1.14,52.07 1.14,59.05
N$28
  Top 0.203: 12.45,62.23 12.45,69.47 9.53,69.47 9.53,62.23 12.45,62.23
N$29
  Top 0.406: 69.85,65.91 69.85,69.72 73.03,67.82 69.85,65.91
N$30
  Top 0.406: 73.03,65.91 73.03,69.72
N$31
  Top 0.406: 67.94,70.48 67.94,73.03 66.67,71.75 67.94,70.48
N$32
  Top 0.406: 66.67,70.48 66.67,73.03
N$33
  Top 0.406: 74.3,70.48 74.3,73.03 73.03,71.75 74.3,70.48
N$34
  Top 0.406: 73.03,70.48 73.03,73.03
N$46  (via drill 0.71)
  Top 0.203: v19.05,25.02 18.16,25.02 IC6.10 | v21.34,27.3 21.34,36.32 19.81,37.85 19.81,39.12 X1.2
  Bottom 0.203: v19.05,25.02 v21.34,27.3
N$47  (via drill 0.71)
  Top 0.203: v23.5,29.59 23.5,36.7 24.64,37.85 24.64,39.12 X1.1 | IC6.11 v25.4,24.77
  Bottom 0.203: v25.4,24.77 25.4,27.69 v23.5,29.59
N$49  (via drill 0.71)
  Top 0.203: v25.27,19.68 25.65,19.3 25.65,17.27 25.15,17.27 IC7.19 | v15.11,33.53 14.48,34.16 14.48,35.69 15.11,36.32 16.26,36.32 IC6.1
  Bottom 0.203: v25.27,19.68 23.11,19.68 18.03,24.77 18.03,30.61 v15.11,33.53
N$50  (via drill 0.71)
  Top 0.203: v24.38,25.91 24.38,17.91 IC7.20 | v15.37,34.92 IC6.2
  Bottom 0.203: v24.38,25.91 v15.37,34.92
N$51
  Top 0.203: IC7.1 19.05,17.91 19.05,22.99 20.45,24.38 20.45,32.51 19.3,33.66 IC6.3
N$52
  Top 0.203: IC7.2 18.41,17.27 18.03,17.27 18.03,22.61 19.94,24.51 19.94,31.75 19.3,32.38 IC6.4
N$53  (via drill 0.71)
  Top 0.203: v21.08,16.38 19.3,16.38 IC7.3 | v33.02,36.32 28.19,36.32 IC6.20
  Bottom 0.203: v21.08,16.38 19.94,16.38 19.3,15.75 19.3,14.99 20.57,13.72 26.67,13.72 27.43,14.48 29.59,14.48 33.02,17.91 v33.02,36.32
N$54  (via drill 0.71)
  Top 0.203: v14.22,18.92 17.27,15.88 18.41,15.88 IC7.4 | v24.77,34.92 IC6.19
  Bottom 0.203: v14.22,18.92 14.22,40.01 15.75,41.53 18.16,41.53 v24.77,34.92
N$55  (via drill 0.71)
  Top 0.203: v20.19,15.37 20.19,15.24 19.3,15.24 IC7.5 | v26.67,19.81 29.21,19.81 33.53,24.26 33.53,33.66 IC6.18
  Bottom 0.203: v20.19,15.37 22.23,15.37 v26.67,19.81
N$56  (via drill 0.71)
  Top 0.203: v22.61,34.92 22.61,16.51 20.57,14.48 19.3,14.48 IC7.6 | v25.4,32.38 IC6.17
  Bottom 0.203: v22.61,34.92 22.86,34.92 v25.4,32.38
N$57  (via drill 0.71)
  Top 0.203: v12.95,18.29 17.27,13.97 18.41,13.97 IC7.7 | v12.95,28.96 15.11,31.11 IC6.5
  Bottom 0.203: v12.95,18.29 v12.95,28.96
N$58  (via drill 0.71)
  Top 0.203: v23.11,14.99 20.7,13.34 19.3,13.34 IC7.8 | v28.83,20.7 33.02,24.89 33.02,30.99 28.19,30.99 IC6.16
  Bottom 0.203: v23.11,14.99 v28.83,20.7
N$59  (via drill 0.71)
  Top 0.203: v17.53,12.7 18.41,12.7 IC7.9 | v15.37,29.84 IC6.6
  Bottom 0.203: v17.53,12.7 17.53,27.69 v15.37,29.84
POR
  Top 0.203: 58.04,19.18 58.04,24 57.91,24 Q2.1 | 58.04,19.18 C15.2 | R14.1 D5.A 58.04,19.18
USB-CC-LIMIT
  Top 0.203: 59.56,28.83 59.56,40.89 57.66,42.8 52.32,42.8 IC5.5 | 59.56,28.83 R5.2 59.05,24.38 64.77,24.38 64.77,11.43 D2.K | 59.56,28.83 C11.2
USB-D+1  (via drill 0.71)
  Top 0.203: v29.08,28.7 28.19,28.7 IC6.14
  Bottom 0.203: v29.08,28.7 29.08,31.88 18.92,42.04 10.29,42.04 8.89,40.64 8.89,39.5 J2.3
USB-D-1  (via drill 0.71)
  Top 0.203: J2.2 12.32,40.26 13.97,40.26 R15.1 v16.13,40.64 | v29.08,27.3 IC6.13
  Bottom 0.203: v29.08,27.3 22.35,34.04 22.23,34.04 16.13,40.13 v16.13,40.64
USB-LIMIT
  Top 0.203: 38.23,17.65 29.97,17.65 28.83,16.51 28.83,12.83 28.45,12.45 25.78,12.45 25.78,13.21 25.15,13.21 IC7.13
~WE1
  Top 0.203: IC7.17 24.38,15.88 23.11,15.88 23.11,27.81 25.15,29.84 IC6.15

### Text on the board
Top: PD | L | 0.4A | COM | PWR+ | 100mA | 200mA | Mini-Laser Driver Rev:A A. Steinberg Labs | University of Toronto, Physics, Quantum Optics
Target: Mini-Laser Driver | A. Steinberg Labs | A.Stummer Mar'04 | A | WHITE WIRE: Error on Rev:A layout, reverse IC2.2 and .3. | Uses Hammond 1591S box.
